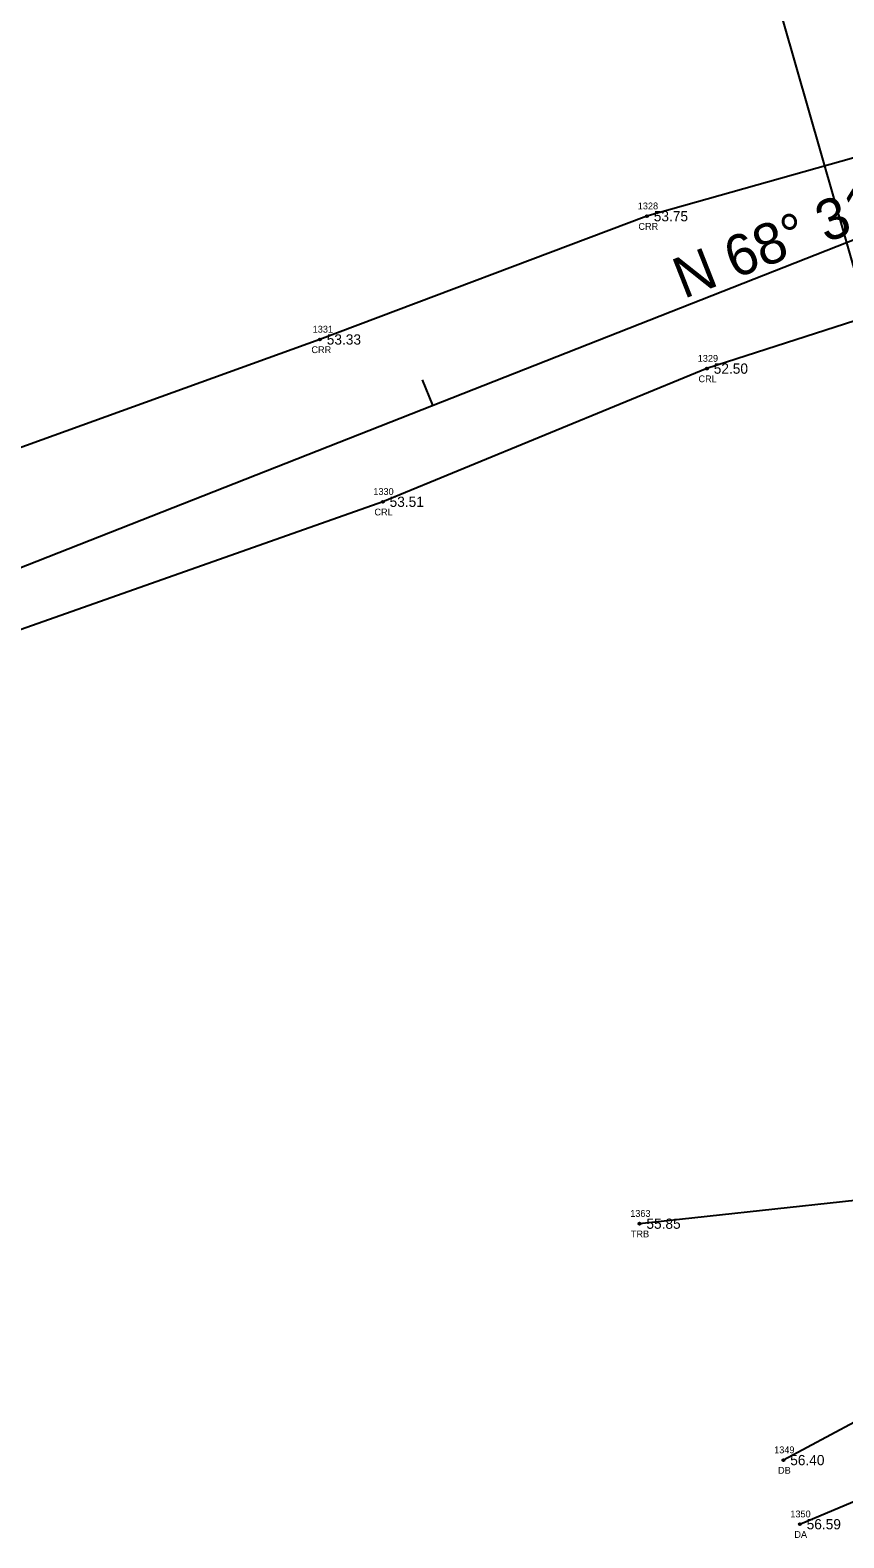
# Model space of a CAD drawing. Extents: x 2396531 to 2397633, y 770203 to 772837.
# Drawn here: x 2396890.9 to 2397010.1, y 771175.7 to 771396.5 of the extents above; entities that cross this region are included whole.
import ezdxf

# ---------------------------------------------------------------- set-up
doc = ezdxf.new("R2010")
doc.units = 0
for name, color, linetype in [('RD_EX_Driveway', 7, 'Continuous'), ('RD_EX_Driveway_txCode', 7, 'Continuous'), ('RD_EX_H2O', 7, 'Continuous'), ('RD_EX_H2O_txCode', 7, 'Continuous'), ('RD_EX_TX_Driveway_ELEV', 7, 'Continuous'), ('RD_EX_TX_H2O_ELEV', 7, 'Continuous'), ('RD_EX_TX_VEG_ELEV', 7, 'Continuous'), ('RD_EX_VEG', 7, 'Continuous'), ('RD_EX_VEG_txCode', 7, 'Continuous'), ('RD_HC_Cl', 7, 'Continuous'), ('RD_HC_Data', 7, 'Continuous'), ('RD_HC_Data_Tic', 7, 'Continuous'), ('RD_SMD_Locator', 7, 'Continuous')]:
    doc.layers.add(name, color=color, linetype=linetype)

msp = doc.modelspace()

# ---------------------------------------------------------------- linework, layer by layer
at = {"layer": 'RD_EX_Driveway'}
for p, q in [((2397048.88, 771212.46), (2397001.22, 771187.05)), ((2397003.63, 771177.66), (2397056.23, 771199.84))]:
    msp.add_line(p, q, dxfattribs=at)
at = {"layer": 'RD_EX_H2O'}
for points in [[(2397026.41, 771393.39), (2397025.73, 771381.74), (2396981.24, 771369.21), (2396933.35, 771351.16), (2396867.1, 771327.21), (2396805.16, 771301.5), (2396726.77, 771268.25), (2396662.72, 771245.88), (2396570.19, 771208.11)], [(2397041.52, 771355.95), (2397038.66, 771356.79), (2397028.89, 771358.5), (2397025.33, 771358.42), (2397018.97, 771356.22), (2396990.02, 771346.89), (2396942.55, 771327.39), (2396877.94, 771304.58), (2396814.23, 771281.47), (2396733.01, 771246.09), (2396670.48, 771223.24), (2396582.44, 771186.21)]]:
    msp.add_lwpolyline(points, dxfattribs=at)
at = {"layer": 'RD_EX_VEG'}
msp.add_lwpolyline([(2396666.35, 772324.52), (2396746.5, 772348.13), (2396878.43, 771953.6), (2396907.83, 771806.94), (2396910.04, 771736.08), (2396945.43, 771592.11), (2397049.51, 771229.15), (2396980.16, 771221.67)], dxfattribs=at)
at = {"layer": 'RD_HC_Cl'}
msp.add_line((2396577.63, 771195.09), (2397449.32, 771538.02), dxfattribs=at)
at = {"layer": 'RD_HC_Data_Tic'}
msp.add_line((2396949.86, 771341.53), (2396948.39, 771345.25), dxfattribs=at)
at = {"layer": 'RD_SMD_Locator'}
for centre in [(2396981.24, 771369.21), (2396933.35, 771351.16), (2396990.02, 771346.89), (2396942.55, 771327.39), (2396980.16, 771221.67), (2397001.22, 771187.05), (2397003.63, 771177.66)]:
    msp.add_circle(centre, 0.15, dxfattribs=at)

# ---------------------------------------------------------------- texts
at = {"layer": 'RD_EX_Driveway_txCode'}
for s, p in [('1349', (2396999.87, 771188.05)), ('DB', (2397000.44, 771185.05)), ('1350', (2397002.24, 771178.66)), ('DA', (2397002.83, 771175.66))]:
    msp.add_text(s, height=1, dxfattribs=at).set_placement(p)
at = {"layer": 'RD_EX_H2O_txCode'}
for s, p in [('1328', (2396979.9, 771370.21)), ('CRR', (2396979.99, 771367.21)), ('1331', (2396932.29, 771352.16)), ('CRR', (2396932.1, 771349.16)), ('1329', (2396988.68, 771347.89)), ('CRL', (2396988.79, 771344.89)), ('1330', (2396941.17, 771328.39)), ('CRL', (2396941.33, 771325.39))]:
    msp.add_text(s, height=1, dxfattribs=at).set_placement(p)
at = {"layer": 'RD_EX_TX_Driveway_ELEV'}
for s, p in [('56.40', (2397002.22, 771186.3)), ('56.59', (2397004.63, 771176.91))]:
    msp.add_text(s, height=1.5, dxfattribs=at).set_placement(p)
at = {"layer": 'RD_EX_TX_H2O_ELEV'}
for s, p in [('53.75', (2396982.24, 771368.46)), ('53.33', (2396934.35, 771350.41)), ('52.50', (2396991.02, 771346.14)), ('53.51', (2396943.55, 771326.64))]:
    msp.add_text(s, height=1.5, dxfattribs=at).set_placement(p)
at = {"layer": 'RD_EX_TX_VEG_ELEV'}
msp.add_text('55.85', height=1.5, dxfattribs=at).set_placement((2396981.16, 771220.92))
at = {"layer": 'RD_EX_VEG_txCode'}
for s, p in [('1363', (2396978.79, 771222.67)), ('TRB', (2396978.89, 771219.67))]:
    msp.add_text(s, height=1, dxfattribs=at).set_placement(p)
at = {"layer": 'RD_HC_Data'}
msp.add_text('N 68%%d 31\' 30" E', height=6, rotation=21.4751, dxfattribs=at).set_placement((2396986.62, 771357.06))

doc.saveas('drawing.dxf')
